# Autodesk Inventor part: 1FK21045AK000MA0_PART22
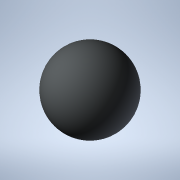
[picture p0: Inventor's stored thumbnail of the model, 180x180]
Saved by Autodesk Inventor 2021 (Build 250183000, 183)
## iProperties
Created: 2025-04
Part Number: 1FK21045AK000MA0_PART22
Material: Generic
Catalog Web Link: www.3dfindit.com
Description: -Servo synchronous motor
Document SubType Name: Modeling
Designer: psAdmin
Mass: 0.137258 g
Surface Area: 1.2868 cm^2
Volume: 0.137258 cm^3
Density: 1 g/cm^3
Appearance: PSOLRGB-212-217-219
Category: PARTsolutions
Title: 1FK21045AK000MA0_PART22
Author: Cadenas PARTsolutions
Comments: Servo synchronous motor
Sending System: PARTsolutions
Preprocessor: ST-DEVELOPER v19.3
PSOL_IDENT_0: {$CADENAS_DATA/23d-libs/siemens_ag/_cat_/3d/2f/1fk21045ak000ma0.prj},216 {VTYP=3D},{NB=1FK21045AK000
PSOL_IDENT_1: MA0_PART22},{LINA=1FK21045AK000MA0_PART22},{NN=1FK21045AK000MA0_PART22},{NOPRJ=TRUE},{DATE=19.08.202
PSOL_IDENT_2: 5 14:00:34},{GEOMDATE=30.07.2025 02:01:24},{VERSION=},{LINEID=10},{WBVAR=},{WBNUMERIC=}  {NB=1FK2104
PSOL_IDENT_3: 5AK000MA0_PART22},{LINA=1FK21045AK000MA0_PART22},{KT=DUMMY},{PREVIEW=../../../_pool_/a9/69/p_d211_xx
PSOL_IDENT_4: _00818j.png},{DESCSHORT=SIMOTICS S-1FK2 HD, SINAMICS S210 3AC 400V-480V, 1.7 Nm, 6000 rpm},{DESCLONG=
PSOL_IDENT_5: SIMOTICS S-1FK2 HD servo motor M0=2.4 Nm; PN = 1.07 kW at nN=6000 rpm (380-480 V); PN = 0.75 kW at n
PSOL_IDENT_6: N=3000 rpm (200-240 V); degree of protection IP64; cylindrical shaft D19x40mm; absolute encoder 22-b
PSOL_IDENT_7: it + 12-bit multiturn (encoder AM22DQC); with OCC interface; plug size M17, rotatable; SIMOTICS S-1F
PSOL_IDENT_8: K2 servomotorfor a wide range of uses in industrial environments. SIMOTICS S‑1FK2 servomotors are co
PSOL_IDENT_9: mpact synchronous motors with a high dynamic performance that set themselves apart as a result of th
PSOL_IDENT_10: eir high power density, degree of protection and overload capability. The motors are available in tw
PSOL_IDENT_11: o variants: as High Dynamic variant (highest dynamic performance as a result of the low intrinsic mo
PSOL_IDENT_12: ment of inertia for applications demanding a high dynamic performance with low moved masses) - and a
PSOL_IDENT_13: s Compact variant (precise and stable closed-loop control for medium up to large moved masses as a r
PSOL_IDENT_14: esult of a medium intrinsic moment of inertia). SIMOTICSS‑1FK2 servomotors fully exploit their stren
PSOL_IDENT_15: gths in a system with the SINAMICSS210 frequency converter and simple connection using the one cable
PSOL_IDENT_16: connection (OCC). Advantages include the short control and positioning times, fast and precise corr
PSOL_IDENT_17: ection of disturbing quantities as well as stable control with a high dynamic performance. The servo
PSOL_IDENT_18: motors can be configured to address a wide range of requirements. For example with and without hold
PSOL_IDENT_19: ing brake, IP64 or IP65 degree of protection, singleturn or multiturn absolute encoders - to name ju
PSOL_IDENT_20: st a few. Further, the servomotors are available in different shaft heights extending from 20 to 100
PSOL_IDENT_21: . A shaft sealing ring is available to achieve an IP65 degree of protection and for subsequent mount
PSOL_IDENT_22: ing at the motor or as spare part. SIMOTICS - the optimum motor for each and every motion control ap
PSOL_IDENT_23: plication.},{INTNO=804766789342},{SUPPLIERALTNO=1FK2104-5AK00-0MA0},{MANUID=1FK21045AK000MA0},{MANUN
PSOL_IDENT_24: AME=Siemens},{MANUTYPEDESC=Synchronous motor 1FK2-HD 2,39 Nm},{AAU732=SIMOTICS},{AAO057=S-1FK2},{AAU
PSOL_IDENT_25: 734=SIMOTICS S-1FK2 HD servo motor M0=2.4 Nm; PN = 1.07 kW at nN=6000 rpm (380-480 V); PN = 0.75 kW
PSOL_IDENT_26: at nN=3000 rpm (200-240 V); degree of protection IP64; cylindrical shaft D19x40mm; absolute encoder
PSOL_IDENT_27: 22-bit + 12-bit multiturn (encoder AM22DQC); with OCC interface; plug size M17, rotatable;},{AAW338=
PSOL_IDENT_28: Synchronous motor 1FK2-HD 2,39 Nm},{AAO742=SIMOTICS},{AAO663=4042948691151},{NOCUPEROU=1},{PRICEQUAN
PSOL_IDENT_29: TITY=1},{QUANTITYMIN=1},{QUANTITYINT=1},{CTN=85015100},{COO=DE},{AAO676=1FK2104-5AK00-0MA0},{AAO677=
PSOL_IDENT_30: Siemens AG},{ORDERUNIT=C62},{CONTENTUNIT=C62}
NB: 1FK21045AK000MA0_PART22
NT: Servo synchronous motor
NBSYN: $MANUID._PART22
LINA: 1FK21045AK000MA0_PART22
CATALOG: SIEMENS
PREVIEW: ../../../_pool_/a9/69/p_d211_xx_00818j.png
DESCSHORT: SIMOTICS S-1FK2 HD, SINAMICS S210 3AC 400V-480V, 1.7 Nm, 6000 rpm
DESCLONG: SIMOTICS S-1FK2 HD servo motor M0=2.4 Nm; PN = 1.07 kW at nN=6000 rpm (380-480 V); PN = 0.75 kW at nN=3000 rpm (200-240 V); degree of protection IP64; cylindric
INTNO: 804766789342
SUPPLIERALTNO: 1FK2104-5AK00-0MA0
MANUID: 1FK21045AK000MA0
MANUNAME: Siemens
MANUTYPEDESC: Synchronous motor 1FK2-HD 2,39 Nm
AAU732: SIMOTICS
AAO057: S-1FK2
AAU734: SIMOTICS S-1FK2 HD servo motor M0=2.4 Nm; PN = 1.07 kW at nN=6000 rpm (380-480 V); PN = 0.75 kW at nN=3000 rpm (200-240 V); degree of protection IP64; cylindric
AAW338: Synchronous motor 1FK2-HD 2,39 Nm
AAO742: SIMOTICS
AAO663: 4042948691151.0
NOCUPEROU: 1
PRICEQUANTITY: 1
QUANTITYMIN: 1
QUANTITYINT: 1
CTN: 85015100
COO: DE
ARTICLENO: 1FK21045AK000MA0_PART22
BOMINFO: 1FK21045AK000MA0_PART22
CREATOR: CADENAS GmbH
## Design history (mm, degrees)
feature "2025_04_17_15_39_51_0728"
body "Solid1"
